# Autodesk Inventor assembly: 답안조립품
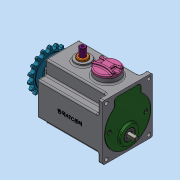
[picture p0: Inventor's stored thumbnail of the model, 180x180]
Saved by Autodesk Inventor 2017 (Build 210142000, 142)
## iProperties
Part Number: 답안조립품
Material: 일반
Document SubType Name: Assembly
Designer: MRC
Author: MRC
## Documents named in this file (16)
- C:\Users\MRC\Desktop\720212V1010\답안조립품.iam
- C:\Users\MRC\Desktop\720212V1010\본체.ipt
- C:\Users\MRC\Desktop\720212V1010\멈춤나사 M3.ipt
- C:\Users\MRC\Desktop\720212V1010\메인 축.ipt
- C:\Users\MRC\Desktop\720212V1010\베어링 608.ipt
- C:\Users\MRC\Desktop\720212V1010\베어링 6003.ipt
- C:\Users\MRC\Desktop\720212V1010\볼트 M4 x 10.ipt
- C:\Users\MRC\Desktop\720212V1010\부시.ipt
- C:\Users\MRC\Desktop\720212V1010\상부 캡.ipt
- C:\Users\MRC\Desktop\720212V1010\서브 축.ipt
- C:\Users\MRC\Desktop\720212V1010\스프로킷.ipt
- C:\Users\MRC\Desktop\720212V1010\슬라이더.ipt
- C:\Users\MRC\Desktop\720212V1010\오일 실 8 x 22 x 7.ipt
- C:\Users\MRC\Desktop\720212V1010\오일 실 17 x 32 x 8.ipt
- C:\Users\MRC\Desktop\720212V1010\커버.ipt
- C:\Users\MRC\Desktop\720212V1010\키 5 x 5.ipt
